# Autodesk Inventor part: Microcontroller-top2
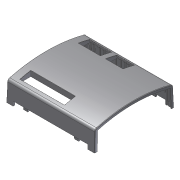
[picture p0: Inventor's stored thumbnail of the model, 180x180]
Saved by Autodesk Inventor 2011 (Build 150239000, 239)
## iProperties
Created: 2010-06
Part Number: Microcontroller-top2
Document SubType Name: Modeling
Designer: kurdi
Density: 1 g/cm^3
Author: kurdi
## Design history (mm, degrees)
sketch "Sketch26"
  geometry: L1 (0, 0)-(1.499, 0) reference; L2 (1.499, 15.011)-(1.499, 0) reference; L3 (0, 15.011)-(0, 0) reference; L4 (1.499, 2.311)-(0, 2.311); 1 further point
  constraints: 2 end point, 2 point on line, 1 perpendicular
  dimensions: "d262" = 2.3114 distance between parallel lines of L4 L1
extrude "Extrusion23" join sketch "Sketch26" distance "d263" = 0.381; taper "d264" = 0 deg
sketch "Sketch27"
  geometry: L1 (0, -15.011)-(1.462, -15.011) reference; L2 (1.462, 0)-(1.462, -15.011) reference; L3 (0, 0)-(0, -15.011) reference; L4 (1.462, -12.7)-(0, -12.7); 1 further point
  constraints: 2 end point, 2 point on line, 1 perpendicular
  dimensions: "d265" = 2.3114 distance between parallel lines of L1 L4
extrude "Extrusion24" join sketch "Sketch27" distance "d266" = 1.27; taper "d267" = 0 deg
sketch "Sketch23"
  geometry: L1 (12.369, -4.386)-(12.369, -1.469) reference; L2 (13.831, -1.469)-(13.831, -4.386) reference; L3 (-13.691, -17.585)-(-13.691, -19.86) reference; L4 (-12.192, -19.86)-(-12.192, -17.585) reference; L5 (19.545, -1.446)-(-45.822, -1.446) reference; L6 (-2.81, -83.725)-(-6.57, -83.725) reference; L7 (-13.691, -85.351)-(-12.192, -85.351); L8 (-12.192, -85.351)-(-12.192, -84.335); L9 (-12.192, -84.335)-(-13.691, -84.335); L10 (-13.691, -84.335)-(-13.691, -85.351); L11 (13.831, -0.836)-(12.369, -0.836); L12 (12.369, -0.836)-(12.369, 0.18); L13 (12.369, 0.18)-(13.831, 0.18); L14 (13.831, 0.18)-(13.831, -0.836); L15 (-12.192, -0.836)-(-13.691, -0.836); L16 (-13.691, -0.836)-(-13.691, 0.18); L17 (-13.691, 0.18)-(-12.192, 0.18); L18 (-12.192, 0.18)-(-12.192, -0.836); 5 further points
  constraints: 24 end point, 8 collinear, 6 parallel, 3 horizontal, 3 perpendicular
  dimensions: "d250" = 0.6096 distance between parallel lines of L9 L6; "d251" = 1.016 distance of L7.end L8.end; "d252" = 0.6096 distance between parallel lines of L11 L5; "d253" = 1.016 distance of L11.end L12.end
extrude "Extrusion20" join sketch "Sketch23" distance "d254" = 15.0114; taper "d255" = 0 deg
sketch "Sketch24"
  geometry: L1 (-13.691, -17.585)-(-13.691, -19.86) reference; L2 (-12.192, -19.86)-(-12.192, -17.585) reference; L3 (-13.691, -1.446)-(-12.192, -1.446); L4 (-12.192, -1.446)-(-12.192, -0.43); L5 (-12.192, -0.43)-(-13.691, -0.43); L6 (-13.691, -0.43)-(-13.691, -1.446); L7 (19.545, -1.446)-(-45.822, -1.446) reference; 3 further points
  constraints: 8 end point, 3 collinear, 2 parallel, 1 horizontal, 1 perpendicular
  dimensions: "d256" = 1.016 distance of L3.end L4.end
extrude "Extrusion21" join sketch "Sketch24" stored distance "d257" = 15.0114; taper "d258" = 0 deg
sketch "Sketch25"
  geometry: L1 (0, 0)-(1.499, 0) reference; L2 (1.499, 15.011)-(1.499, 0) reference; L3 (0, 15.011)-(0, 0) reference; L4 (1.499, 2.159)-(0, 2.159); 1 further point
  constraints: 2 end point, 2 point on line, 1 perpendicular
  dimensions: "d259" = 2.159 distance between parallel lines of L1 L4
extrude "Extrusion22" join sketch "Sketch25" distance "d260" = 1.524; taper "d261" = 0 deg
sketch "Sketch21"
  geometry: L1 (7.33, -82.524)-(7.33, -84.372) reference; L2 (6.09, -84.372)-(6.09, -82.524) reference; L3 (2.33, -84.372)-(1.09, -84.372) reference; L4 (2.33, -82.524)-(2.33, -84.372) reference; L5 (1.09, -82.524)-(2.33, -82.524) reference; L6 (1.09, -84.372)-(1.09, -82.524) reference; L7 (-1.57, -84.372)-(-2.81, -84.372) reference; L8 (-1.57, -82.524)-(-1.57, -84.372) reference; L9 (-2.81, -82.524)-(-1.57, -82.524) reference; L10 (-2.81, -84.372)-(-2.81, -82.524) reference; L11 (-6.57, -84.372)-(-7.81, -84.372) reference; L12 (-6.57, -82.524)-(-6.57, -84.372) reference; L13 (-7.81, -82.524)-(-6.57, -82.524) reference; L14 (-7.81, -84.372)-(-7.81, -82.524) reference; L15 (-18.51, -84.372)-(-19.75, -84.372) reference; L16 (-18.51, -82.524)-(-18.51, -84.372) reference; L17 (-19.75, -82.524)-(-18.51, -82.524) reference; L18 (-19.75, -84.372)-(-19.75, -82.524) reference; L19 (-25.11, -84.372)-(-26.35, -84.372) reference; L20 (-25.11, -84.372)-(-25.11, -82.524) reference; L21 (-25.11, -82.524)-(-26.35, -82.524) reference; L22 (-26.35, -82.524)-(-26.35, -84.372) reference; L23 (-30.01, -84.372)-(-31.25, -84.372) reference; L24 (-30.01, -84.372)-(-30.01, -82.524) reference; L25 (-30.01, -82.524)-(-31.25, -82.524) reference; L26 (-31.25, -82.524)-(-31.25, -84.372) reference; L27 (-36.61, -84.372)-(-37.85, -84.372) reference; L28 (-36.61, -84.372)-(-36.61, -82.524) reference; L29 (-36.61, -82.524)-(-37.85, -82.524) reference; L30 (-37.85, -82.524)-(-37.85, -84.372) reference; L31 (-40.41, -84.372)-(-41.61, -84.372) reference; L32 (-40.41, -84.372)-(-40.41, -70.027) reference; L33 (-40.41, -70.027)-(-15.971, -70.027) reference; L34 (-15.971, -70.027)-(-15.971, -83.676) reference; L35 (-15.971, -83.676)-(-14.75, -83.676) reference; L36 (-14.75, -83.676)-(-14.75, -69.806) reference; L37 (-15.75, -68.806)-(-40.75, -68.806) reference; L38 (-41.61, -69.257)-(-41.61, -75.941) reference; L39 (-41.61, -81.631)-(-41.61, -84.372) reference; L40 (-41.61, -85.351)-(-40.41, -85.351); L41 (-40.41, -85.351)-(-40.41, -84.335); L42 (-40.41, -84.335)-(-41.61, -84.335); L43 (-41.61, -84.335)-(-41.61, -85.351); L44 (-37.85, -85.351)-(-36.61, -85.351); L45 (-36.61, -85.351)-(-36.61, -84.335); L46 (-36.61, -84.335)-(-37.85, -84.335); L47 (-37.85, -84.335)-(-37.85, -85.351); L48 (-31.25, -85.351)-(-30.01, -85.351); L49 (-30.01, -85.351)-(-30.01, -84.335); L50 (-30.01, -84.335)-(-31.25, -84.335); L51 (-31.25, -84.335)-(-31.25, -85.351); L52 (-26.35, -85.351)-(-25.11, -85.351); L53 (-25.11, -85.351)-(-25.11, -84.335); L54 (-25.11, -84.335)-(-26.35, -84.335); L55 (-26.35, -84.335)-(-26.35, -85.351); L56 (-19.75, -85.351)-(-18.51, -85.351); L57 (-18.51, -85.351)-(-18.51, -84.335); L58 (-18.51, -84.335)-(-19.75, -84.335); L59 (-19.75, -84.335)-(-19.75, -85.351); L60 (-7.81, -85.351)-(-6.57, -85.351); L61 (-6.57, -85.351)-(-6.57, -84.335); L62 (-6.57, -84.335)-(-7.81, -84.335); L63 (-7.81, -84.335)-(-7.81, -85.351); L64 (-2.81, -85.351)-(-1.57, -85.351)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; C1 r 1 at (-42.2, -67.086) reference; C2 r 1.15 at (-41.91, -78.786) reference; A1 r 1 centre (-15.75, -69.806) between (-14.75, -69.806) and (-15.75, -68.806) reference; A2 r 2.25 centre (-42.2, -67.086) between (-40.75, -68.806) and (-41.61, -69.257) reference; A3 r 2.861 centre (-41.91, -78.786) between (-41.61, -75.941) and (-41.61, -81.631) reference; 1 further point
  constraints: 72 end point, 34 collinear, 18 parallel, 9 horizontal, 9 perpendicular
  dimensions: "d240" = 0.6096 distance between parallel lines of L42 L76; "d241" = 1.016 distance of L42.end L40.start
extrude "Extrusion18" join sketch "Sketch21" distance "d242" = 8.001; taper "d243" = 0 deg
sketch "Sketch22"
  geometry: L1 (1.499, -17.225)-(1.499, 0) reference; L2 (0, 0)-(0, -17.225) reference; L3 (1.499, -16.578)-(21.831, -16.578) reference; L4 (1.499, 65.701)-(21.831, 65.701) reference; L5 (0, 67.327)-(1.499, 67.327); L6 (1.499, 67.327)-(1.499, 66.311); L7 (1.499, 66.311)-(0, 66.311); L8 (0, 66.311)-(0, 67.327); L9 (0, -18.204)-(1.499, -18.204); L10 (1.499, -18.204)-(1.499, -17.188); L11 (1.499, -17.188)-(0, -17.188); L12 (0, -17.188)-(0, -18.204); 1 further point
  constraints: 16 end point, 4 collinear, 4 parallel, 2 horizontal, 2 perpendicular
  dimensions: "d244" = 0.6096 distance between parallel lines of L7 L4; "d245" = 1.016 distance of L5.end L6.end; "d246" = 0.6096 distance between parallel lines of L11 L3; "d247" = 1.016 distance of L9.end L10.end
extrude "Extrusion19" join sketch "Sketch22" distance "d248" = 3.5052; taper "d249" = 0 deg
node "Projected Loop16"
node "Projected Loop17"
node "Projected Loop18"
extrude "Extrusion17" join sketch "Sketch20" distance "d238" = 8.001; taper "d239" = 0 deg
node "Projected Loop11"
node "Projected Loop12"
node "Projected Loop13"
node "Projected Loop14"
node "Projected Loop15"
sketch "Sketch18"
  geometry: L1 (-22.276, 156.917)-(-22.276, 156.41) reference; L2 (22.276, 156.41)-(22.276, 156.917) reference; L3 (22.276, 156.917)-(22.276, 156.923); L4 (-22.276, 156.917)-(-22.276, 156.923); A1 r 158.496 centre (0, 0) between (41.846, 152.872) and (-41.846, 152.872) reference; A2 r 157.988 centre (0, 0) between (22.276, 156.41) and (-22.276, 156.41) reference; 1 further point
  constraints: 4 end point, 2 point on circle, 1 collinear, 1 parallel
extrude "Extrusion16" cut sketch "Sketch18" stored distance "d228" = 0.9906; taper "d229" = 0 deg
workplane "Work Plane6"
sketch "Sketch19"
  geometry: L1 (41.09, 20.32)-(27.22, 20.32) reference; L2 (41.09, 20.32)-(27.553, 20.32); A1 r 157.988 centre (0, -131.686) between (23.241, 24.583) and (-23.241, 24.583) reference; A2 r 154.483 centre (0, -131.686) between (27.553, 20.32) and (-22.725, 21.116); 1 further point
  constraints: 2 end point, 2 point on circle, 1 centre point, 1 collinear
  dimensions: "d231" = 3.5052 radial gap between concentric circles of A2 A1
feature "Rib3" dims "d232" = 2.54, "d233" = 1.4986, "d234" = 0
sketch "Sketch17"
  geometry: L1 (62.504, -0.525)-(71.567, -0.525) reference; L2 (71.567, -0.525)-(71.567, -0.258) reference; L3 (59.944, 2.588)-(59.944, 0) reference; L4 (52.248, 3.879)-(52.248, 2.904); L5 (7.696, 3.879)-(7.696, 2.904); L6 (53.213, 3.738)-(53.213, 2.762); L7 (6.731, 3.738)-(6.731, 2.762); L8 (6.731, 3.738)-(6.731, 4.246); L9 (7.696, 3.879)-(7.696, 4.386); L10 (53.213, 3.738)-(53.213, 4.246); L11 (52.248, 3.879)-(52.248, 4.386); A1 r 157.988 centre (29.972, -152.531) between (0, 2.588) and (-11.168, 0.006) reference; A2 r 1.016 centre (70.847, -0.974) between (71.567, -0.258) and (71.112, 0.006) reference; A3 r 157.988 centre (29.972, -152.531) between (71.112, 0.006) and (59.944, 2.588) reference; A4 r 157.988 centre (29.972, -152.531) between (52.248, 3.879) and (7.696, 3.879); A5 r 157.023 centre (29.972, -152.531) between (52.248, 2.904) and (7.696, 2.904); A6 r 157.988 centre (29.972, -152.531) between (53.213, 3.738) and (52.248, 3.879); A7 r 157.023 centre (29.972, -152.531) between (53.213, 2.762) and (52.248, 2.904); A8 r 157.988 centre (29.972, -152.531) between (7.696, 3.879) and (6.731, 3.738); A9 r 157.023 centre (29.972, -152.531) between (7.696, 2.904) and (6.731, 2.762); A10 r 155.448 centre (29.972, -152.531) between (62.504, -0.525) and (59.944, 0) reference; A11 r 158.49 centre (29.972, -152.531) between (7.696, 4.386) and (6.731, 4.246); A12 r 158.49 centre (29.972, -152.531) between (53.213, 4.246) and (52.248, 4.386); A13 r 158.49 centre (29.972, -152.531) between (52.248, 4.386) and (7.696, 4.386); 5 further points
  constraints: 24 point on circle, 16 end point, 9 centre point, 9 concentric, 5 parallel, 2 vertical, 1 collinear, 2 other
  dimensions: "d209" = 22.2758 horizontal distance of L4.start point (29.972, -20.845); "d210" = 22.2758 horizontal distance of L5.start point (29.972, -20.845) (derived); "d212" = 23.241 distance from line of L6 point (29.972, -20.845); "d213" = 23.241 distance from line of L7 point (29.972, -20.845); "d221" = 0.508 distance of L7.start L8.end
extrude "Extrusion14" join sketch "Sketch17" distance "d223" = 2.9718; taper "d224" = 0 deg
extrude "Extrusion15" join sketch "Sketch17" distance "d225" = 0.9906; taper "d226" = 0 deg
node "Projected Loop3"
mirror "Mirror7"
sketch "Sketch15"
  geometry: L1 (41.957, 17.998)-(42.4, 5.309) reference; L2 (-42.4, 5.309)-(-41.957, 17.998) reference; L3 (41.957, 17.998)-(41.846, 21.186); L4 (-41.957, 17.998)-(-41.846, 21.186); A1 r 157.988 centre (0, -131.686) between (41.14, 20.852) and (-41.14, 20.852) reference; A2 r 158.496 centre (0, -131.686) between (41.846, 21.186) and (-41.846, 21.186); A3 r 155.453 centre (0, -131.686) between (41.957, 17.998) and (-41.957, 17.998); 1 further point
  constraints: 4 end point, 4 point on circle, 2 centre point, 2 collinear, 1 concentric
  dimensions: "d220" = 0.508 radial gap between concentric circles of A2 A1
extrude "Extrusion12" cut sketch "Sketch15" stored distance "d196" = 2.9972; taper "d197" = 0 deg
mirror "Mirror8"
sketch "Sketch16"
  geometry: L1 (42.4, -5.309)-(42.4, 20.994); L2 (12.428, 18.125)-(12.428, 15.011); L3 (12.435, 14.061)-(72.372, 14.061); L4 (72.372, 15.011)-(72.372, 18.125); L5 (10.264, 15.011)-(15.729, 15.011) reference; L6 (0.805, 0)-(0.805, 15.279) reference; L7 (12.428, 15.011)-(0.805, 15.011); L8 (12.435, 14.061)-(12.435, 12.471); L9 (12.435, 12.471)-(0.805, 12.471); L10 (0.805, 12.471)-(0.805, 15.011); L11 (83.995, 0)-(83.995, 15.279) reference; L12 (72.372, 15.011)-(83.995, 15.011); L13 (72.372, 12.471)-(83.995, 12.471); L14 (83.995, 15.011)-(83.995, 12.471); L15 (72.372, 12.471)-(72.372, 14.061); A1 r 157.988 centre (42.4, -136.994) between (83.54, 15.543) and (1.261, 15.543) reference; A2 r 157.988 centre (42.4, -136.994) between (72.372, 18.125) and (12.428, 18.125)
  constraints: 24 end point, 7 collinear, 5 point on circle, 4 point on line, 2 parallel, 2 perpendicular, 1 centre point, 1 concentric, 1 horizontal, 1 vertical
  dimensions: "d198" = 29.972 distance from line of L1 L2.start; "d199" = 29.972 distance from line of L4.end L1; "d201" = 4.064 distance of L2.start L3.start; "d205" = 2.54 distance of L9.end L7.end; "d208" = 71.55993 distance between parallel lines of L11 L8
extrude "Extrusion13" cut sketch "Sketch16" stored distance "d202" = 2.9972; taper "d203" = 0 deg
sketch "Sketch13"
  geometry: L1 (-83.676, 11.13)-(-69.806, 11.13); L2 (-83.676, 9.909)-(-83.676, 11.13); L3 (-83.676, 9.909)-(-70.027, 9.909); L4 (-70.027, 9.909)-(-70.027, -9.429); L5 (-70.027, -9.429)-(-83.676, -9.429); L6 (-83.676, -10.65)-(-83.676, -9.429); L7 (-69.806, -10.65)-(-83.676, -10.65); L8 (-68.806, 10.13)-(-68.806, -9.65); L9 (-68.806, 15.75)-(-68.806, 40.75); L10 (-75.941, 41.61)-(-69.257, 41.61); L11 (-85.023, 41.61)-(-81.631, 41.61); L12 (-85.023, 40.41)-(-70.027, 40.41); L13 (-70.027, 40.41)-(-70.027, 15.971); L14 (-70.027, 15.971)-(-83.676, 15.971); L15 (-83.676, 14.75)-(-83.676, 15.971); L16 (-69.806, 14.75)-(-83.676, 14.75); L17 (-82.524, 36.61)-(-82.524, 37.85); L18 (-85.023, 37.85)-(-82.524, 37.85); L19 (-82.524, 36.61)-(-85.023, 36.61); L20 (-82.524, 30.01)-(-82.524, 31.25); L21 (-85.023, 31.25)-(-82.524, 31.25); L22 (-82.524, 30.01)-(-85.023, 30.01); L23 (-82.524, 25.11)-(-82.524, 26.35); L24 (-85.023, 26.35)-(-82.524, 26.35); L25 (-82.524, 25.11)-(-85.023, 25.11); L26 (-82.524, 18.51)-(-85.023, 18.51); L27 (-82.524, 18.51)-(-82.524, 19.75); L28 (-85.023, 19.75)-(-82.524, 19.75); L29 (-82.524, 6.57)-(-85.023, 6.57); L30 (-82.524, 6.57)-(-82.524, 7.81); L31 (-85.023, 7.81)-(-82.524, 7.81); L32 (-82.524, 1.57)-(-85.023, 1.57); L33 (-82.524, 1.57)-(-82.524, 2.81); L34 (-85.023, 2.81)-(-82.524, 2.81); L35 (-82.524, -2.33)-(-85.023, -2.33); L36 (-82.524, -2.33)-(-82.524, -1.09); L37 (-85.023, -1.09)-(-82.524, -1.09); L38 (-82.524, -7.33)-(-85.023, -7.33); L39 (-82.524, -7.33)-(-82.524, -6.09); L40 (-85.023, -6.09)-(-82.524, -6.09); L41 (-15.914, 41.61)-(-10.45, 41.61); L42 (-17.585, -9.65)-(-17.585, 40.006); L43 (-1.496, -10.65)-(-16.585, -10.65); L44 (-1.496, -9.429)-(-1.496, -10.65); L45 (-1.496, -9.429)-(-16.364, -9.429); L46 (-16.364, -9.429)-(-16.364, 40.41); L47 (-16.364, 40.41)-(-1.469, 40.41); L48 (-4.76, 41.61)-(-1.469, 41.61); L49 (-4.386, 37.65)-(-1.469, 37.65); L50 (-4.386, 37.65)-(-4.386, 36.41); L51 (-1.469, 36.41)-(-4.386, 36.41); L52 (-4.386, 27.05)-(-4.386, 25.81); L53 (-1.469, 25.81)-(-4.386, 25.81); L54 (-4.386, 27.05)-(-1.469, 27.05); L55 (-4.386, 23.15)-(-4.386, 21.91); L56 (-1.469, 21.91)-(-4.386, 21.91); L57 (-4.386, 23.15)-(-1.469, 23.15); L58 (-4.386, 9.05)-(-4.386, 7.81); L59 (-1.469, 7.81)-(-4.386, 7.81); L60 (-4.386, 9.05)-(-1.469, 9.05); L61 (-4.386, 5.15)-(-4.386, 3.91); L62 (-1.469, 3.91)-(-4.386, 3.91); L63 (-4.386, 5.15)-(-1.469, 5.15); L64 (-4.386, -5.45)-(-4.386, -6.69)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; C1 r 1 at (-67.086, 42.2); C2 r 1.15 at (-78.786, 41.91); C3 r 1 at (-18.086, 42.2); C4 r 1.15 at (-7.605, 41.91); A1 r 1 centre (-69.806, 10.13) between (-68.806, 10.13) and (-69.806, 11.13); A2 r 1 centre (-69.806, -9.65) between (-69.806, -10.65) and (-68.806, -9.65); A3 r 2.25 centre (-67.086, 42.2) between (-68.806, 40.75) and (-69.257, 41.61); A4 r 2.861 centre (-78.786, 41.91) between (-75.941, 41.61) and (-81.631, 41.61); A5 r 1 centre (-69.806, 15.75) between (-69.806, 14.75) and (-68.806, 15.75); A6 r 2.861 centre (-7.605, 41.91) between (-4.76, 41.61) and (-10.45, 41.61); A7 r 2.25 centre (-18.086, 42.2) between (-15.914, 41.61) and (-17.585, 40.006); A8 r 1 centre (-16.585, -9.65) between (-17.585, -9.65) and (-16.585, -10.65); 2 further points
  constraints: 172 end point, 45 collinear, 38 horizontal, 16 point on circle, 12 centre point, 9 perpendicular, 9 vertical, 8 parallel, 8 tangent, 4 concentric
  dimensions: "d121" = 10.64981 distance from line of L43 point (-42.586, 0); "d122" = 25.00099 distance from line of point (-42.586, 0) L42; "d123" = 26.22019 distance from line of L8 point (-42.586, 0); "d124" = 10.64981 distance from line of L7 point (-42.586, 0); "d125" = 1.71928 distance between parallel lines of L67 L43; "d126" = 1.22094 distance of L44.start L43.start; "d127" = 1.46181 distance of L67.end L69.start; "d128" = 1.23963 distance of L66.end L65.start; "d130" = 9.36037 distance between parallel lines of L62 L66; "d131" = 2.66037 distance between parallel lines of L59 L63; "d132" = 12.86037 distance between parallel lines of L56 L60; "d133" = 2.66037 distance between parallel lines of L53 L57; "d134" = 9.36037 distance between parallel lines of L51 L54; "d135" = 2.91644 distance of L69.start L68.start; "d136" = 13.19902 distance between parallel lines of L42 L68; "d137" = 0.99995 radius of A8; "d139" = 41.09 distance from line of L44 point (-42.586, 0); "d140" = 1.22094 distance between parallel lines of L43 L45; "d141" = 49.83869 distance of L45.end L46.end; "d142" = 2.86083 radius of A6; "d143" = 2.3 diameter of C4; "d144" = 2.25 radius of A7; "d145" = 2 diameter of C3; "d147" = 0.59019 distance from line of L41 A7.centre; "d148" = 1.2 distance between parallel lines of L47 L41; "d149" = 9.97981 distance from line of L42 A6.centre; "d150" = 0.30019 distance from line of L41 A6.centre; "d151" = 5.67928 distance between parallel lines of L67 L65; "d152" = 1.22094 distance between parallel lines of L4 L8; "d153" = 0.99995 radius of A2; "d154" = 0.99995 radius of A1; "d155" = 0.99995 radius of A5; "d156" = 1.22094 distance between parallel lines of L1 L3; "d157" = 1.22094 distance between parallel lines of L7 L5; "d158" = 14.86981 distance between parallel lines of L8 L6; "d159" = 2.49802 distance of L40.start L39.end; "d160" = 39.93887 distance from line of point (-42.586, 0) L39; "d161" = 7.32981 distance from line of point (-42.586, 0) L38; "d162" = 1.23963 distance of L40.start L38.end; "d163" = 3.76037 distance between parallel lines of L35 L40; "d164" = 2.66037 distance between parallel lines of L32 L37; "d165" = 3.76037 distance between parallel lines of L29 L34; "d166" = 19.33774 distance of L3.end L4.end; "d167" = 14.86981 distance between parallel lines of L8 L2; "d168" = 10.70037 distance between parallel lines of L26 L31; "d169" = 3.62037 distance between parallel lines of L1 L16; "d170" = 1.22094 distance between parallel lines of L16 L14; "d171" = 5.36037 distance between parallel lines of L25 L28; "d172" = 3.66037 distance between parallel lines of L22 L24; "d173" = 5.36037 distance between parallel lines of L19 L21; "d174" = 24.43869 distance of L12.end L13.end; "d175" = 1.2 distance between parallel lines of L10 L12; "d176" = 9.97981 distance from line of L9 A4.centre; "d177" = 1.72019 distance from line of L9 A3.centre; "d178" = 2.25 radius of A3; "d179" = 2 diameter of C1; "d180" = 0.59019 distance from line of L10 A3.centre; "d181" = 2.86083 radius of A4; "d182" = 2.3 diameter of C2; "d183" = 0.30019 distance from line of L10 C2.centre; "d184" = 42.33564 distance from line of point (-43.805, 0) L86; "d185" = 13.8309 distance from line of point (-43.805, 0) L69; "d268" = 24.5 horizontal distance of point (-42.586, 0) A7.centre; "d269" = 26.22193 distance from line of L46 point (-42.586, 0)
extrude "Extrusion10" join sketch "Sketch13" stored distance "d186" = 2.9972; taper "d187" = 0 deg
sketch "Sketch14"
  geometry: L1 (-40.41, -84.372)-(-40.41, -70.027) reference; L2 (-40.41, -70.027)-(-15.971, -70.027) reference; L3 (-15.971, -70.027)-(-15.971, -83.676) reference; L4 (-9.909, -83.676)-(-9.909, -70.027) reference; L5 (-9.909, -70.027)-(9.429, -70.027) reference; L6 (9.429, -70.027)-(9.429, -83.676) reference; L7 (9.429, -16.364)-(-40.41, -16.364) reference; L8 (-40.41, -16.364)-(-40.41, -1.469) reference; L9 (9.429, -1.496)-(9.429, -16.364) reference; L10 (-5.15, -4.386)-(-3.91, -4.386) reference; L11 (-25.11, -82.524)-(-26.35, -82.524) reference; L12 (-15.971, -82.524)-(-40.41, -82.524); L13 (-40.41, -82.524)-(-40.41, -70.027); L14 (-40.41, -70.027)-(-15.971, -70.027); L15 (-15.971, -70.027)-(-15.971, -82.524); L16 (-9.909, -70.027)-(9.429, -70.027); L17 (9.429, -70.027)-(9.429, -82.524); L18 (9.429, -82.524)-(-9.909, -82.524); L19 (-9.909, -82.524)-(-9.909, -70.027); L20 (-40.41, -4.386)-(9.429, -4.386); L21 (9.429, -4.386)-(9.429, -16.364); L22 (9.429, -16.364)-(-40.41, -16.364); L23 (-40.41, -16.364)-(-40.41, -4.386); 2 further points
  constraints: 24 end point, 12 collinear, 6 parallel, 3 horizontal, 3 perpendicular
extrude "Extrusion11" cut sketch "Sketch14" stored distance "d188" = 2.9972; taper "d189" = 0 deg
chamfer "Chamfer1" distance "d190" = 0.254; stored, may be unused: second distance "d191" = 3.175, angle "d192" = 45 deg
sketch "Sketch10"
  geometry: L1 (-32.07, 20.32)-(-24.562, 20.32); L2 (24.562, 20.32)-(32.07, 20.32); L3 (-33.34, 22.744)-(-33.34, 20.32) reference; L4 (33.34, 20.32)-(33.34, 22.744) reference; A1 r 158.757 centre (0, -136.525) between (24.562, 20.32) and (-24.562, 20.32); 1 further point
  constraints: 4 end point, 2 horizontal, 2 point on circle, 1 centre point, 1 collinear, 1 vertical alignment
  dimensions: "d105" = 136.525 distance of point (0, 0) A1.centre; "d106" = 20.32 distance from line of point (0, 0) L1; "d107" = 1.27 distance from line of L3 L1.start; "d108" = 1.27 distance from line of L4 L2.end
feature "Rib2" sketch "Sketch10" dims "d109" = 2.54, "d110" = 1.4986, "d111" = 0
mirror "Mirror2"
sketch "Sketch11"
  geometry: L1 (-41.91, 0)-(41.91, 0); L2 (41.91, 0)-(41.91, 4.801); L3 (41.91, 4.801)-(-41.91, 4.801); L4 (-41.91, 4.801)-(-41.91, 0); 2 further points
  constraints: 8 end point, 2 parallel, 1 coincident, 1 horizontal, 1 midpoint, 1 perpendicular
  dimensions: "d112" = 83.82 distance of L1.start L1.end; "d113" = 4.8006 distance of L3.end L1.start
extrude "Extrusion8" cut sketch "Sketch11" stored distance "d114" = 8.001; taper "d115" = 0 deg
sketch "Sketch12"
  geometry: L1 (0, 0)-(83.82, 0) reference; L2 (0, -2.032)-(0, 0) reference; L3 (10.897, -1.499)-(15.9, -1.499); L4 (15.9, -1.499)-(15.9, 0); L5 (15.9, 0)-(10.897, 0); L6 (10.897, 0)-(10.897, -1.499); 1 further point
  constraints: 8 end point, 2 parallel, 1 collinear, 1 horizontal, 1 perpendicular
  dimensions: "d116" = 5.0038 distance of L3.start L3.end; "d117" = 10.8966 distance between parallel lines of L6 L2; "d118" = 1.4986 distance of L3.end L4.end
extrude "Extrusion9" join sketch "Sketch12" distance "d119" = 2.9972; taper "d120" = -2 deg
mirror "Mirror3"
mirror "Mirror4"
node "Projected Loop1"
node "Projected Loop2"
sketch "Sketch8"
  geometry: L1 (0, 2.032)-(48.895, 2.032) reference; L2 (49.53, -0.965)-(49.53, 1.397) reference; L3 (46.761, -0.991)-(45.568, -0.991); L4 (45.568, -0.991)-(45.568, 0.406); L5 (45.568, 0.406)-(46.761, 0.406); L6 (46.761, 0.406)-(46.761, -0.991); L7 (45.568, 0)-(45.568, -0.656) reference; L8 (45.568, 0.406)-(45.568, 0) reference; L9 (45.568, -0.656)-(45.568, 0.406) reference; L10 (45.568, 0.406)-(43.358, 0.406) reference; L11 (43.358, 0.406)-(45.568, 0.406) reference; 1 further point
  constraints: 8 end point, 2 collinear, 2 parallel, 1 horizontal, 1 perpendicular
  dimensions: "d89" = 3.0226 distance between parallel lines of L1 L3; "d90" = 1.1938 distance of L3.start L3.end
extrude "Extrusion7" join sketch "Sketch8" stored distance "d91" = 8.001; taper "d92" = 0 deg
mirror "Mirror1"
workplane "Work Plane4"
sketch "Sketch9"
  geometry: L1 (-32.07, 22.809)-(-21.201, 22.809); L2 (21.201, 22.809)-(32.07, 22.809); L3 (-33.34, 22.744)-(-33.34, 20.32) reference; L4 (33.34, 20.32)-(33.34, 22.744) reference; A1 r 155.956 centre (0, -131.699) between (21.201, 22.809) and (-21.201, 22.809); 1 further point
  constraints: 4 end point, 2 horizontal, 2 point on circle, 1 centre point, 1 collinear, 1 vertical alignment
  dimensions: "d95" = 22.8092 distance from line of point (0, 0) L1; "d96" = 1.27 distance from line of L3 L1.start; "d97" = 1.27 distance from line of L4 L2.end; "d98" = 131.699 distance of point (0, 0) A1.centre; "d99" = 155.956 radius of A1
feature "Rib1" dims "d100" = 2.54, "d101" = 1.4986, "d102" = 0
workplane "Work Plane5"
sketch "Sketch6"
  geometry: L1 (0, 2.032)-(48.895, 2.032) reference; L2 (49.53, -0.965)-(49.53, 1.397) reference; L3 (41.377, -0.508)-(42.367, -0.508); L4 (42.367, -0.508)-(42.367, -3.548); L5 (41.377, -3.548)-(41.377, -0.508); C1 r 1.156 at (41.872, -6.375); A1 r 2.87 centre (41.872, -6.375) between (41.377, -3.548) and (42.367, -3.548); 2 further points
  constraints: 6 end point, 2 centre point, 2 point on circle, 1 coincident, 1 horizontal, 1 midpoint, 1 parallel, 1 perpendicular, 1 vertical alignment
  dimensions: "d74" = 2.54 distance between parallel lines of L1 L3; "d75" = 8.4074 distance from line of C1.centre L1; "d76" = 0.9906 distance of L3.start L3.end; "d77" = 7.1628 distance between parallel lines of L2 L4; "d78" = 2.3114 diameter of C1; "d79" = 2.8702 radius of A1
extrude "Extrusion5" join sketch "Sketch6" stored distance "d80" = 25.4; taper "d81" = 0 deg
sketch "Sketch7"
  geometry: L1 (41.377, -3.548)-(41.377, -0.799) reference; L2 (42.367, -0.799)-(42.367, -3.548) reference; L3 (42.367, -0.838)-(41.377, -0.838); L4 (41.377, -0.838)-(41.377, 0.178); L5 (41.377, 0.178)-(42.367, 0.178); L6 (42.367, 0.178)-(42.367, -0.838); L7 (42.367, -1.446)-(45.822, -1.446) reference; A1 r 2.87 centre (41.872, -6.375) between (41.377, -3.548) and (42.367, -3.548) reference; 1 further point
  constraints: 8 end point, 2 collinear, 2 parallel, 1 horizontal, 1 perpendicular
  dimensions: "d82" = 5.5372 distance from line of L3 A1.centre; "d83" = 1.016 distance of L3.end L4.end; "d235" = 0.60776 distance between parallel lines of L3 L7 (derived)
extrude "Extrusion6" join sketch "Sketch7" distance "d84" = 8.001; taper "d85" = 0 deg
workplane "Work Plane3"
fillet "Fillet2" dims "d58" = 0.635
sketch "Sketch4"
  geometry: L1 (0, 0)-(48.514, 0) reference; L2 (48.514, 0)-(48.514, -0.66) reference; L3 (49.53, -0.965)-(49.53, 1.397) reference; L4 (45.568, -2.134)-(45.568, 0.406); L5 (43.358, -2.134)-(43.358, 0.406); L6 (43.358, 0.406)-(45.568, 0.406); L7 (43.358, -2.134)-(45.568, -2.134); 1 further point
  constraints: 8 end point, 3 parallel, 1 perpendicular
  dimensions: "d59" = 2.9464 distance between parallel lines of L2 L4; "d60" = 2.2098 distance between parallel lines of L5 L4; "d62" = 0.4064 distance between parallel lines of L1 L6; "d63" = 2.54 distance between parallel lines of L7 L6
extrude "Extrusion3" cut sketch "Sketch4" distance "d64" = 18.796; taper "d65" = 0 deg
workplane "Work Plane1"
sketch "Sketch5"
  geometry: L1 (-42.156, 17.937)-(-42.156, 20.574); L2 (42.156, 17.937)-(42.156, 20.574); A1 r 157.988 centre (0, -131.686) between (41.14, 20.852) and (-41.14, 20.852) reference; A2 r 155.448 centre (0, -131.686) between (42.156, 17.937) and (-42.156, 17.937); A3 r 157.988 centre (0, -131.686) between (-41.14, 20.852) and (-42.156, 20.574); A4 r 157.988 centre (0, -131.686) between (42.156, 20.574) and (41.14, 20.852); 1 further point
  constraints: 6 point on circle, 4 end point, 3 centre point, 3 concentric, 1 parallel, 1 vertical
  dimensions: "d217" = 2.54 radial gap between concentric circles of A2 A1; "d218" = 1.016 distance from line of L1 A1.end; "d219" = 1.016 distance from line of L2 A1.start
extrude "Extrusion4" join sketch "Sketch5" distance "d70" = 1.4986; taper "d71" = 0 deg
fillet "Fillet3" dims "d72" = 0.635
workplane "Work Plane2"
sketch "Sketch2"
  geometry: L1 (-41.89, 19.906)-(-42.586, 0); L2 (-44.618, 0)-(-43.92, 19.978); L3 (-42.418, 4.801)-(-44.45, 4.801); L4 (27.334, 20.32)-(26.113, 20.32); L5 (27.286, 25.781)-(27.334, 20.32); L6 (27.028, 26.035)-(27.286, 25.781); L7 (26.113, 20.32)-(26.08, 24.135); L8 (39.918, 22.934)-(40.176, 23.188); L9 (39.902, 21.18)-(39.918, 22.934); L10 (42.586, 0)-(41.89, 19.906); L11 (44.45, 4.801)-(42.418, 4.801); L12 (43.92, 19.978)-(44.618, 0); L13 (40.176, 23.188)-(40.254, 23.188); L14 (44.45, 4.801)-(44.45, 30.201); L15 (-44.45, 4.801)-(-44.45, 30.201); L16 (44.618, 0)-(42.586, 0); L17 (-42.586, 0)-(-44.618, 0); A1 r 1.016 centre (-40.875, 19.871) between (-41.14, 20.852) and (-41.89, 19.906); A2 r 3.048 centre (-40.874, 19.871) between (-41.668, 22.814) and (-43.92, 19.978); A3 r 160.02 centre (0, -131.686) between (41.668, 22.814) and (-41.668, 22.814); A4 r 157.988 centre (0, -131.686) between (41.14, 20.852) and (-41.14, 20.852); A5 r 1.016 centre (40.875, 19.871) between (41.89, 19.906) and (41.14, 20.852); A6 r 3.048 centre (40.874, 19.871) between (43.92, 19.978) and (41.668, 22.814); 4 further points
  constraints: 34 end point, 16 point on circle, 8 tangent, 6 centre point, 4 point on line, 3 collinear, 3 horizontal, 3 parallel, 2 horizontal alignment, 2 midpoint, 1 concentric, 1 vertical
  dimensions: "d3" = 3.048 radius of A6; "d6" = 160.02 radius of A3; "d7" = 157.988 radius of A4; "d9" = 2 deg angle of L14 L10; "d10" = 2 deg angle of L2 L15; "d11" = 2 deg angle of L15 L1; "d14" = 3.048 radius of A2; "d18" = 19.9898 distance of L12.start L12.end; "d19" = 4.8006 distance between parallel lines of L16 L11; "d20" = 4.8006 distance between parallel lines of L17 L3; "d22" = 0.5 deg angle of L14 L9; "d23" = 1.28017 distance of L9.start A4.start; "d25" = 135 deg angle of L8 L9; "d26" = 0.07757 distance of L8.end L13.end; "d28" = 1 deg angle of L5 L9; "d29" = 20.32 distance between parallel lines of L4 L16; "d30" = 1.22094 distance of L4.start L4.end; "d31" = 19.9898 distance of L2.start L2.end; "d32" = 2.032 distance of L12.end L10.start; "d33" = 89.23523 distance of L2.start L12.end; "d34" = 44.61761 distance of point (0, 0) L12.end; "d35" = 3.81478 vertical distance of L4.end L7.end; "d39" = 25.4 distance from line of L14.end L11; "d40" = 44.45 distance from line of point (0, 0) L14; "d42" = 25.4 distance from line of L15.end L11; "d43" = 45 deg angle of L6 L5; "d44" = 0.254 vertical distance of L6.start L5.start; "d45" = 1.016 radius of A1; "d46" = 2 deg angle of L14 L12; "d47" = 1.016 radius of A5; "d48" = 0.254 vertical distance of L8.start L8.end
extrude "Extrusion1" new body sketch "Sketch2" distance "d49" = 49.53; taper "d50" = 0 deg
sketch "Sketch3"
  geometry: L1 (43.92, 19.978)-(44.618, 0) reference; L2 (-44.618, 0)-(-43.92, 19.978) reference; L3 (-41.62, 0)-(-40.925, 19.91); L4 (40.925, 19.91)-(41.62, 0); L5 (-44.618, 0)-(-41.62, 0); L6 (44.618, 0)-(41.62, 0); A1 r 160.02 centre (0, -131.686) between (41.668, 22.814) and (-41.668, 22.814) reference; A2 r 157.023 centre (0, -131.686) between (40.925, 19.91) and (-40.925, 19.91); A3 r 3.048 centre (40.874, 19.871) between (43.92, 19.978) and (41.668, 22.814) reference; A4 r 3.048 centre (-40.874, 19.871) between (-41.668, 22.814) and (-43.92, 19.978) reference; 1 further point
  constraints: 8 end point, 2 parallel, 2 point on circle, 1 centre point, 1 collinear, 1 horizontal
  dimensions: "d51" = 2.9972 distance of L1.end L4.end; "d52" = 2.9972 distance of L2.start L3.start; "d53" = 2.9972 radial gap between concentric circles of A2 A1
extrude "Extrusion2" join sketch "Sketch3" distance "d54" = 1.016; taper "d55" = 0 deg
feature "FaceDraft1" dims angle "d56" = -1 deg
fillet "Fillet1" dims "d57" = 0.3048
body "Solid1"
other parameters: "d66" = 1.1938, "d73" = -20.32, "d86" = -5.3086, "d93" = -41.8846, "d94" = 22.8092, "d103" = 21.59, "d104" = 20.32, "d230" = -12.9413, "d236" = 0.6096, "d237" = 1.016
